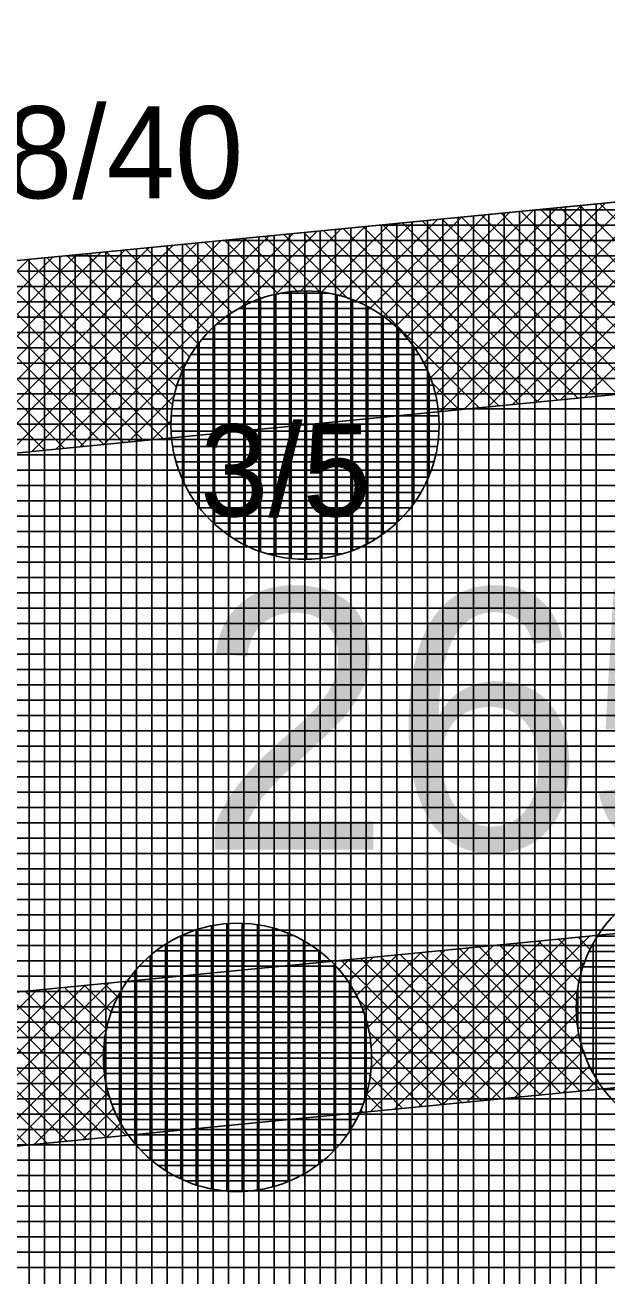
# Model space of a CAD drawing. Extents: x -566461 to -565198, y -1096301 to -1095707.
# Drawn here: x -566336.54 to -566328.95, y -1095853.58 to -1095837.26 of the extents above; entities that cross this region are included whole.
import ezdxf

# ---------------------------------------------------------------- set-up
doc = ezdxf.new("R2010")
doc.units = 0
for name, color, linetype in [('Vrstva 1', 7, 'Continuous'), ('Vrstva 18', 7, 'Continuous'), ('Vrstva 40', 7, 'Continuous'), ('Vrstva 41', 7, 'Continuous'), ('Vrstva 42', 7, 'Continuous'), ('Vrstva 43', 7, 'Continuous'), ('Vrstva 44', 7, 'Continuous')]:
    doc.layers.add(name, color=color, linetype=linetype)

msp = doc.modelspace()

# ---------------------------------------------------------------- linework, layer by layer
at = {"layer": 'Vrstva 1'}
msp.add_line((-566305.22, -1095837.26), (-566355.65, -1095842.19), dxfattribs=at)
at = {"layer": 'Vrstva 41'}
for p, q in [((-566328.028, -1095839.49), (-566330.811, -1095842.273)), ((-566327.714, -1095839.459), (-566330.498, -1095842.243)), ((-566327.401, -1095839.428), (-566330.184, -1095842.212)), ((-566327.087, -1095839.398), (-566329.871, -1095842.181)), ((-566326.774, -1095839.367), (-566329.557, -1095842.151)), ((-566326.46, -1095839.336), (-566329.244, -1095842.12)), ((-566329.595, -1095839.643), (-566331.453, -1095841.501)), ((-566329.282, -1095839.612), (-566331.347, -1095841.678)), ((-566328.968, -1095839.582), (-566331.26, -1095841.874)), ((-566328.655, -1095839.551), (-566331.194, -1095842.091)), ((-566328.341, -1095839.52), (-566331.125, -1095842.304)), ((-566329.558, -1095839.639), (-566328.007, -1095841.19)), ((-566329.3, -1095839.614), (-566327.927, -1095840.987)), ((-566329.042, -1095839.589), (-566327.827, -1095840.804)), ((-566331.162, -1095839.796), (-566332.235, -1095840.869)), ((-566330.849, -1095839.765), (-566332.043, -1095840.96)), ((-566330.535, -1095839.735), (-566331.87, -1095841.069)), ((-566330.222, -1095839.704), (-566331.714, -1095841.197)), ((-566329.909, -1095839.674), (-566331.575, -1095841.34)), ((-566331.361, -1095839.816), (-566329.073, -1095842.103)), ((-566331.104, -1095839.79), (-566328.816, -1095842.078)), ((-566330.846, -1095839.765), (-566328.558, -1095842.053)), ((-566330.588, -1095839.74), (-566328.3, -1095842.028)), ((-566330.331, -1095839.715), (-566328.068, -1095841.977)), ((-566330.073, -1095839.69), (-566328.088, -1095841.675)), ((-566329.815, -1095839.664), (-566328.061, -1095841.418)), ((-566333.043, -1095839.98), (-566335.827, -1095842.764)), ((-566332.73, -1095839.949), (-566333.744, -1095840.963)), ((-566332.416, -1095839.919), (-566333.283, -1095840.785)), ((-566332.103, -1095839.888), (-566332.958, -1095840.743)), ((-566332.907, -1095839.967), (-566330.619, -1095842.255)), ((-566331.789, -1095839.857), (-566332.685, -1095840.753)), ((-566332.649, -1095839.941), (-566330.362, -1095842.229)), ((-566331.476, -1095839.827), (-566332.448, -1095840.798)), ((-566332.392, -1095839.916), (-566330.104, -1095842.204)), ((-566332.134, -1095839.891), (-566329.846, -1095842.179)), ((-566331.876, -1095839.866), (-566329.589, -1095842.154)), ((-566331.619, -1095839.841), (-566329.331, -1095842.129)), ((-566334.611, -1095840.133), (-566336.796, -1095842.318)), ((-566334.297, -1095840.103), (-566336.717, -1095842.523)), ((-566333.984, -1095840.072), (-566336.664, -1095842.752)), ((-566333.67, -1095840.041), (-566336.454, -1095842.825)), ((-566333.357, -1095840.011), (-566336.141, -1095842.794)), ((-566334.711, -1095840.143), (-566333.834, -1095841.02)), ((-566334.453, -1095840.118), (-566333.654, -1095840.917)), ((-566334.195, -1095840.093), (-566333.454, -1095840.834)), ((-566333.938, -1095840.067), (-566333.231, -1095840.774)), ((-566333.68, -1095840.042), (-566332.978, -1095840.744)), ((-566333.422, -1095840.017), (-566332.687, -1095840.752)), ((-566333.165, -1095839.992), (-566332.321, -1095840.836)), ((-566336.178, -1095840.286), (-566337.457, -1095841.565)), ((-566335.865, -1095840.256), (-566337.292, -1095841.683)), ((-566335.551, -1095840.225), (-566337.143, -1095841.817)), ((-566335.238, -1095840.195), (-566337.011, -1095841.967)), ((-566334.924, -1095840.164), (-566336.895, -1095842.134)), ((-566336.257, -1095840.294), (-566334.559, -1095841.991)), ((-566335.999, -1095840.269), (-566334.485, -1095841.783)), ((-566335.741, -1095840.244), (-566334.389, -1095841.596)), ((-566335.484, -1095840.219), (-566334.275, -1095841.427)), ((-566335.226, -1095840.193), (-566334.144, -1095841.275)), ((-566334.968, -1095840.168), (-566333.997, -1095841.139)), ((-566338.06, -1095840.47), (-566335.772, -1095842.758)), ((-566337.803, -1095840.445), (-566335.515, -1095842.733)), ((-566336.492, -1095840.317), (-566337.64, -1095841.465)), ((-566337.545, -1095840.42), (-566335.257, -1095842.708)), ((-566337.287, -1095840.395), (-566334.999, -1095842.683)), ((-566337.03, -1095840.37), (-566334.742, -1095842.658)), ((-566336.772, -1095840.344), (-566334.631, -1095842.486)), ((-566336.514, -1095840.319), (-566334.609, -1095842.224)), ((-566338.318, -1095840.496), (-566336.03, -1095842.784)), ((-566334.407, -1095841.626), (-566335.514, -1095842.733)), ((-566331.246, -1095841.911), (-566330.877, -1095842.28)), ((-566334.585, -1095842.087), (-566335.2, -1095842.702)), ((-566336.815, -1095842.282), (-566336.288, -1095842.809)), ((-566334.627, -1095842.412), (-566334.887, -1095842.672)), ((-566331.162, -1095842.277), (-566331.134, -1095842.305)), ((-566330.119, -1095849.239), (-566332.102, -1095851.222)), ((-566330.432, -1095849.27), (-566332.045, -1095850.883)), ((-566329.805, -1095849.209), (-566332.033, -1095851.436)), ((-566329.492, -1095849.178), (-566331.72, -1095851.406)), ((-566329.178, -1095849.147), (-566331.406, -1095851.375)), ((-566330.357, -1095849.263), (-566329.329, -1095850.291)), ((-566330.1, -1095849.237), (-566329.337, -1095850.001)), ((-566329.842, -1095849.212), (-566329.306, -1095849.748)), ((-566329.584, -1095849.187), (-566329.246, -1095849.526)), ((-566329.327, -1095849.162), (-566329.163, -1095849.326)), ((-566329.069, -1095849.137), (-566329.06, -1095849.145)), ((-566332, -1095849.423), (-566332.33, -1095849.754)), ((-566331.686, -1095849.393), (-566332.225, -1095849.931)), ((-566332.161, -1095849.439), (-566330.33, -1095851.27)), ((-566331.373, -1095849.362), (-566332.139, -1095850.128)), ((-566331.059, -1095849.331), (-566332.073, -1095850.345)), ((-566330.746, -1095849.301), (-566332.037, -1095850.591)), ((-566331.903, -1095849.414), (-566330.072, -1095851.245)), ((-566331.646, -1095849.389), (-566329.815, -1095851.22)), ((-566331.388, -1095849.363), (-566329.557, -1095851.194)), ((-566331.13, -1095849.338), (-566329.299, -1095851.169)), ((-566330.873, -1095849.313), (-566329.042, -1095851.144)), ((-566330.615, -1095849.288), (-566329.244, -1095850.658)), ((-566332.313, -1095849.454), (-566332.453, -1095849.593)), ((-566332.419, -1095849.464), (-566330.588, -1095851.295)), ((-566329.229, -1095849.48), (-566331.093, -1095851.344)), ((-566335.448, -1095849.76), (-566337.676, -1095851.988)), ((-566335.51, -1095849.766), (-566335.325, -1095849.952)), ((-566335.253, -1095849.741), (-566335.222, -1095849.772)), ((-566335.762, -1095849.791), (-566337.989, -1095852.019)), ((-566336.075, -1095849.822), (-566337.866, -1095851.613)), ((-566336.389, -1095849.852), (-566337.827, -1095851.291)), ((-566335.293, -1095849.887), (-566337.362, -1095851.957)), ((-566337.056, -1095849.917), (-566335.225, -1095851.748)), ((-566336.799, -1095849.892), (-566335.427, -1095851.264)), ((-566336.541, -1095849.867), (-566335.501, -1095850.907)), ((-566336.283, -1095849.842), (-566335.505, -1095850.62)), ((-566336.026, -1095849.817), (-566335.473, -1095850.369)), ((-566335.768, -1095849.792), (-566335.41, -1095850.15)), ((-566329.324, -1095849.859), (-566330.779, -1095851.314)), ((-566338.087, -1095850.018), (-566336.256, -1095851.849)), ((-566337.829, -1095849.993), (-566335.998, -1095851.824)), ((-566337.572, -1095849.968), (-566335.741, -1095851.799)), ((-566337.314, -1095849.943), (-566335.483, -1095851.774)), ((-566332.216, -1095849.95), (-566330.845, -1095851.32)), ((-566329.338, -1095850.155), (-566330.466, -1095851.283)), ((-566338.08, -1095850.308), (-566336.514, -1095851.874)), ((-566335.467, -1095850.345), (-566337.049, -1095851.927)), ((-566332.065, -1095850.384), (-566331.103, -1095851.345)), ((-566329.31, -1095850.41), (-566330.152, -1095851.253)), ((-566335.508, -1095850.668), (-566336.735, -1095851.896)), ((-566332.031, -1095850.701), (-566331.361, -1095851.371)), ((-566329.253, -1095850.636), (-566329.839, -1095851.222)), ((-566329.171, -1095850.837), (-566329.525, -1095851.191)), ((-566335.497, -1095850.94), (-566336.422, -1095851.865)), ((-566332.053, -1095850.961), (-566331.618, -1095851.396)), ((-566329.07, -1095851.019), (-566329.212, -1095851.161)), ((-566335.45, -1095851.177), (-566336.108, -1095851.835)), ((-566332.096, -1095851.201), (-566331.876, -1095851.421)), ((-566335.38, -1095851.389), (-566335.795, -1095851.804)), ((-566332.169, -1095851.411), (-566332.134, -1095851.446)), ((-566335.288, -1095851.58), (-566335.481, -1095851.773))]:
    msp.add_line(p, q, dxfattribs=at)
at = {"layer": 'Vrstva 42'}
for points in [[(-566355.65, -1095842.19), (-566355.093, -1095844.647), (-566304.64, -1095839.715), (-566305.22, -1095837.26)], [(-566353.532, -1095851.528), (-566353.085, -1095853.494), (-566302.553, -1095848.555), (-566303.017, -1095846.59)]]:
    msp.add_lwpolyline(points, close=True, dxfattribs=at)
at = {"layer": 'Vrstva 43'}
for p, q in [((-566329.69, -1095839.652), (-566329.69, -1095860.64)), ((-566329.49, -1095839.633), (-566329.49, -1095860.625)), ((-566329.29, -1095839.613), (-566329.29, -1095860.609)), ((-566329.09, -1095839.594), (-566329.09, -1095860.594)), ((-566331.29, -1095839.809), (-566331.29, -1095860.764)), ((-566331.09, -1095839.789), (-566331.09, -1095860.748)), ((-566330.89, -1095839.769), (-566330.89, -1095860.733)), ((-566330.69, -1095839.75), (-566330.69, -1095860.717)), ((-566330.49, -1095839.73), (-566330.49, -1095860.702)), ((-566330.29, -1095839.711), (-566330.29, -1095860.687)), ((-566330.09, -1095839.691), (-566330.09, -1095860.671)), ((-566329.89, -1095839.672), (-566329.89, -1095860.656)), ((-566329.872, -1095839.67), (-566304.651, -1095839.67)), ((-566332.89, -1095839.965), (-566332.89, -1095860.887)), ((-566332.69, -1095839.945), (-566332.69, -1095860.872)), ((-566332.49, -1095839.926), (-566332.49, -1095860.856)), ((-566332.29, -1095839.906), (-566332.29, -1095860.841)), ((-566332.09, -1095839.887), (-566332.09, -1095860.825)), ((-566331.918, -1095839.87), (-566304.604, -1095839.87)), ((-566331.89, -1095839.867), (-566331.89, -1095860.81)), ((-566331.69, -1095839.848), (-566331.69, -1095860.794)), ((-566331.49, -1095839.828), (-566331.49, -1095860.779)), ((-566334.69, -1095840.141), (-566334.69, -1095861.026)), ((-566334.49, -1095840.121), (-566334.49, -1095861.01)), ((-566334.29, -1095840.102), (-566334.29, -1095860.995)), ((-566334.09, -1095840.082), (-566334.09, -1095860.979)), ((-566333.964, -1095840.07), (-566304.557, -1095840.07)), ((-566333.89, -1095840.063), (-566333.89, -1095860.964)), ((-566333.69, -1095840.043), (-566333.69, -1095860.949)), ((-566333.49, -1095840.024), (-566333.49, -1095860.933)), ((-566333.29, -1095840.004), (-566333.29, -1095860.918)), ((-566333.09, -1095839.985), (-566333.09, -1095860.902)), ((-566336.29, -1095840.297), (-566336.29, -1095861.149)), ((-566336.09, -1095840.278), (-566336.09, -1095861.134)), ((-566336.01, -1095840.27), (-566304.51, -1095840.27)), ((-566335.89, -1095840.258), (-566335.89, -1095861.118)), ((-566335.69, -1095840.239), (-566335.69, -1095861.103)), ((-566335.49, -1095840.219), (-566335.49, -1095861.087)), ((-566335.29, -1095840.2), (-566335.29, -1095861.072)), ((-566335.09, -1095840.18), (-566335.09, -1095861.057)), ((-566334.89, -1095840.161), (-566334.89, -1095861.041)), ((-566338.056, -1095840.47), (-566304.463, -1095840.47)), ((-566336.49, -1095840.317), (-566336.49, -1095861.164)), ((-566340.102, -1095840.67), (-566304.416, -1095840.67)), ((-566342.147, -1095840.87), (-566304.368, -1095840.87)), ((-566344.193, -1095841.07), (-566304.321, -1095841.07)), ((-566346.239, -1095841.27), (-566304.274, -1095841.27)), ((-566348.285, -1095841.47), (-566304.227, -1095841.47)), ((-566350.331, -1095841.67), (-566304.18, -1095841.67)), ((-566352.377, -1095841.87), (-566304.132, -1095841.87)), ((-566354.423, -1095842.07), (-566304.085, -1095842.07)), ((-566355.632, -1095842.27), (-566304.038, -1095842.27)), ((-566355.586, -1095842.47), (-566303.991, -1095842.47)), ((-566355.541, -1095842.67), (-566303.944, -1095842.67)), ((-566355.496, -1095842.87), (-566303.897, -1095842.87)), ((-566355.45, -1095843.07), (-566303.849, -1095843.07)), ((-566355.405, -1095843.27), (-566303.802, -1095843.27)), ((-566355.36, -1095843.47), (-566303.755, -1095843.47)), ((-566355.314, -1095843.67), (-566303.708, -1095843.67)), ((-566355.269, -1095843.87), (-566303.661, -1095843.87)), ((-566355.223, -1095844.07), (-566303.613, -1095844.07)), ((-566355.178, -1095844.27), (-566303.566, -1095844.27)), ((-566355.133, -1095844.47), (-566303.519, -1095844.47)), ((-566355.087, -1095844.67), (-566303.472, -1095844.67)), ((-566355.042, -1095844.87), (-566303.425, -1095844.87)), ((-566354.997, -1095845.07), (-566303.378, -1095845.07)), ((-566354.951, -1095845.27), (-566303.33, -1095845.27)), ((-566354.906, -1095845.47), (-566303.283, -1095845.47)), ((-566354.861, -1095845.67), (-566303.236, -1095845.67)), ((-566354.815, -1095845.87), (-566303.189, -1095845.87)), ((-566354.77, -1095846.07), (-566303.142, -1095846.07)), ((-566354.724, -1095846.27), (-566303.094, -1095846.27)), ((-566354.679, -1095846.47), (-566303.047, -1095846.47)), ((-566354.634, -1095846.67), (-566303, -1095846.67)), ((-566354.588, -1095846.87), (-566302.953, -1095846.87)), ((-566354.543, -1095847.07), (-566302.906, -1095847.07)), ((-566354.498, -1095847.27), (-566302.859, -1095847.27)), ((-566354.452, -1095847.47), (-566302.811, -1095847.47)), ((-566354.407, -1095847.67), (-566302.764, -1095847.67)), ((-566354.361, -1095847.87), (-566302.717, -1095847.87)), ((-566354.316, -1095848.07), (-566302.67, -1095848.07)), ((-566354.271, -1095848.27), (-566302.623, -1095848.27)), ((-566354.225, -1095848.47), (-566302.575, -1095848.47)), ((-566354.18, -1095848.67), (-566302.528, -1095848.67)), ((-566354.135, -1095848.87), (-566302.481, -1095848.87)), ((-566354.089, -1095849.07), (-566302.434, -1095849.07)), ((-566354.044, -1095849.27), (-566302.387, -1095849.27)), ((-566353.998, -1095849.47), (-566302.34, -1095849.47)), ((-566353.953, -1095849.67), (-566302.292, -1095849.67)), ((-566353.908, -1095849.87), (-566302.245, -1095849.87)), ((-566353.862, -1095850.07), (-566302.198, -1095850.07)), ((-566353.817, -1095850.27), (-566302.151, -1095850.27)), ((-566353.772, -1095850.47), (-566302.104, -1095850.47)), ((-566353.726, -1095850.67), (-566302.056, -1095850.67)), ((-566353.681, -1095850.87), (-566302.009, -1095850.87)), ((-566353.635, -1095851.07), (-566301.962, -1095851.07)), ((-566353.59, -1095851.27), (-566301.915, -1095851.27)), ((-566353.545, -1095851.47), (-566301.868, -1095851.47)), ((-566353.499, -1095851.67), (-566301.821, -1095851.67)), ((-566353.454, -1095851.87), (-566301.773, -1095851.87)), ((-566353.409, -1095852.07), (-566301.726, -1095852.07)), ((-566353.363, -1095852.27), (-566301.679, -1095852.27)), ((-566353.318, -1095852.47), (-566301.632, -1095852.47)), ((-566353.272, -1095852.67), (-566301.585, -1095852.67)), ((-566353.227, -1095852.87), (-566301.537, -1095852.87)), ((-566353.182, -1095853.07), (-566301.49, -1095853.07)), ((-566353.136, -1095853.27), (-566301.443, -1095853.27)), ((-566353.091, -1095853.47), (-566301.396, -1095853.47))]:
    msp.add_line(p, q, dxfattribs=at)
msp.add_lwpolyline([(-566355.65, -1095842.19), (-566351.09, -1095862.29), (-566300.24, -1095858.37), (-566305.22, -1095837.26)], close=True, dxfattribs=at)
at = {"layer": 'Vrstva 44'}
for p, q in [((-566333.27, -1095844.188), (-566333.27, -1095840.774)), ((-566333.21, -1095840.76), (-566332.576, -1095840.76)), ((-566333.07, -1095844.219), (-566333.07, -1095840.741)), ((-566332.87, -1095844.228), (-566332.87, -1095840.73)), ((-566332.67, -1095844.214), (-566332.67, -1095840.745)), ((-566332.47, -1095844.178), (-566332.47, -1095840.783)), ((-566333.753, -1095840.96), (-566332.026, -1095840.96)), ((-566333.67, -1095844.045), (-566333.67, -1095840.914)), ((-566333.47, -1095844.129), (-566333.47, -1095840.831)), ((-566332.27, -1095844.116), (-566332.27, -1095840.845)), ((-566332.07, -1095844.024), (-566332.07, -1095840.934)), ((-566333.87, -1095843.928), (-566333.87, -1095841.032)), ((-566331.87, -1095843.9), (-566331.87, -1095841.06)), ((-566334.07, -1095843.77), (-566334.07, -1095841.189)), ((-566334.036, -1095841.16), (-566331.744, -1095841.16)), ((-566331.67, -1095843.732), (-566331.67, -1095841.226)), ((-566334.27, -1095843.553), (-566334.27, -1095841.407)), ((-566334.232, -1095841.36), (-566331.546, -1095841.36)), ((-566334.377, -1095841.56), (-566331.404, -1095841.56)), ((-566331.47, -1095843.501), (-566331.47, -1095841.46)), ((-566334.484, -1095841.76), (-566331.296, -1095841.76)), ((-566334.47, -1095843.229), (-566334.47, -1095841.729)), ((-566331.27, -1095843.137), (-566331.27, -1095841.822)), ((-566334.559, -1095841.96), (-566331.22, -1095841.96)), ((-566334.609, -1095842.16), (-566331.171, -1095842.16)), ((-566334.635, -1095842.36), (-566331.146, -1095842.36)), ((-566334.638, -1095842.56), (-566331.143, -1095842.56)), ((-566334.616, -1095842.76), (-566331.163, -1095842.76)), ((-566334.571, -1095842.96), (-566331.208, -1095842.96)), ((-566334.501, -1095843.16), (-566331.28, -1095843.16)), ((-566334.402, -1095843.36), (-566331.379, -1095843.36)), ((-566334.264, -1095843.56), (-566331.515, -1095843.56)), ((-566334.082, -1095843.76), (-566331.698, -1095843.76)), ((-566333.822, -1095843.96), (-566331.958, -1095843.96)), ((-566333.379, -1095844.16), (-566332.405, -1095844.16)), ((-566334.31, -1095852.393), (-566334.31, -1095849.067)), ((-566334.11, -1095852.445), (-566334.11, -1095849.015)), ((-566333.91, -1095852.472), (-566333.91, -1095848.986)), ((-566333.71, -1095852.477), (-566333.71, -1095848.982)), ((-566333.51, -1095852.46), (-566333.51, -1095849.001)), ((-566333.31, -1095852.418), (-566333.31, -1095849.043)), ((-566333.11, -1095852.349), (-566333.11, -1095849.11)), ((-566334.71, -1095852.206), (-566334.71, -1095849.255)), ((-566334.51, -1095852.314), (-566334.51, -1095849.146)), ((-566334.497, -1095849.14), (-566333.043, -1095849.14)), ((-566332.91, -1095852.252), (-566332.91, -1095849.208)), ((-566329.13, -1095850.938), (-566329.13, -1095849.244)), ((-566329.074, -1095849.15), (-566326.126, -1095849.15)), ((-566334.91, -1095852.055), (-566334.91, -1095849.405)), ((-566334.833, -1095849.34), (-566332.71, -1095849.34)), ((-566332.71, -1095852.122), (-566332.71, -1095849.34)), ((-566329.186, -1095849.35), (-566326.016, -1095849.35)), ((-566335.11, -1095851.854), (-566335.11, -1095849.607)), ((-566335.051, -1095849.54), (-566332.49, -1095849.54)), ((-566332.51, -1095851.942), (-566332.51, -1095849.518)), ((-566329.263, -1095849.55), (-566325.935, -1095849.55)), ((-566335.211, -1095849.74), (-566332.327, -1095849.74)), ((-566332.31, -1095851.691), (-566332.31, -1095849.767)), ((-566329.315, -1095849.75), (-566325.885, -1095849.75)), ((-566335.31, -1095851.558), (-566335.31, -1095849.903)), ((-566329.33, -1095850.348), (-566329.33, -1095849.827)), ((-566335.33, -1095849.94), (-566332.211, -1095849.94)), ((-566329.343, -1095849.95), (-566325.858, -1095849.95)), ((-566335.417, -1095850.14), (-566332.124, -1095850.14)), ((-566332.11, -1095851.278), (-566332.11, -1095850.178)), ((-566329.348, -1095850.15), (-566325.853, -1095850.15)), ((-566335.475, -1095850.34), (-566332.065, -1095850.34)), ((-566329.33, -1095850.35), (-566325.871, -1095850.35)), ((-566335.51, -1095850.898), (-566335.51, -1095850.563)), ((-566335.508, -1095850.54), (-566332.031, -1095850.54)), ((-566329.287, -1095850.55), (-566325.912, -1095850.55)), ((-566335.518, -1095850.74), (-566332.022, -1095850.74)), ((-566329.219, -1095850.75), (-566325.981, -1095850.75)), ((-566335.506, -1095850.94), (-566332.035, -1095850.94)), ((-566329.124, -1095850.95), (-566326.078, -1095850.95)), ((-566335.471, -1095851.14), (-566332.07, -1095851.14)), ((-566328.99, -1095851.15), (-566326.208, -1095851.15)), ((-566335.408, -1095851.34), (-566332.13, -1095851.34)), ((-566335.319, -1095851.54), (-566332.221, -1095851.54)), ((-566335.199, -1095851.74), (-566332.343, -1095851.74)), ((-566335.032, -1095851.94), (-566332.508, -1095851.94)), ((-566334.803, -1095852.14), (-566332.734, -1095852.14)), ((-566334.453, -1095852.34), (-566333.089, -1095852.34))]:
    msp.add_line(p, q, dxfattribs=at)
for centre in [(-566332.89, -1095842.48), (-566327.6, -1095850.09), (-566333.77, -1095850.73)]:
    msp.add_circle(centre, 1.75, dxfattribs=at)

# ---------------------------------------------------------------- texts
at = {"layer": 'Vrstva 18'}
msp.add_text('2656', height=3.4, dxfattribs=at).set_placement((-566334.298, -1095848.02))
at = {"layer": 'Vrstva 40'}
for s, p in [('18/40', (-566337.71, -1095839.52)), ('3/5', (-566334.26, -1095843.67))]:
    msp.add_text(s, height=1.2, dxfattribs=at).set_placement(p)

doc.saveas('drawing.dxf')
